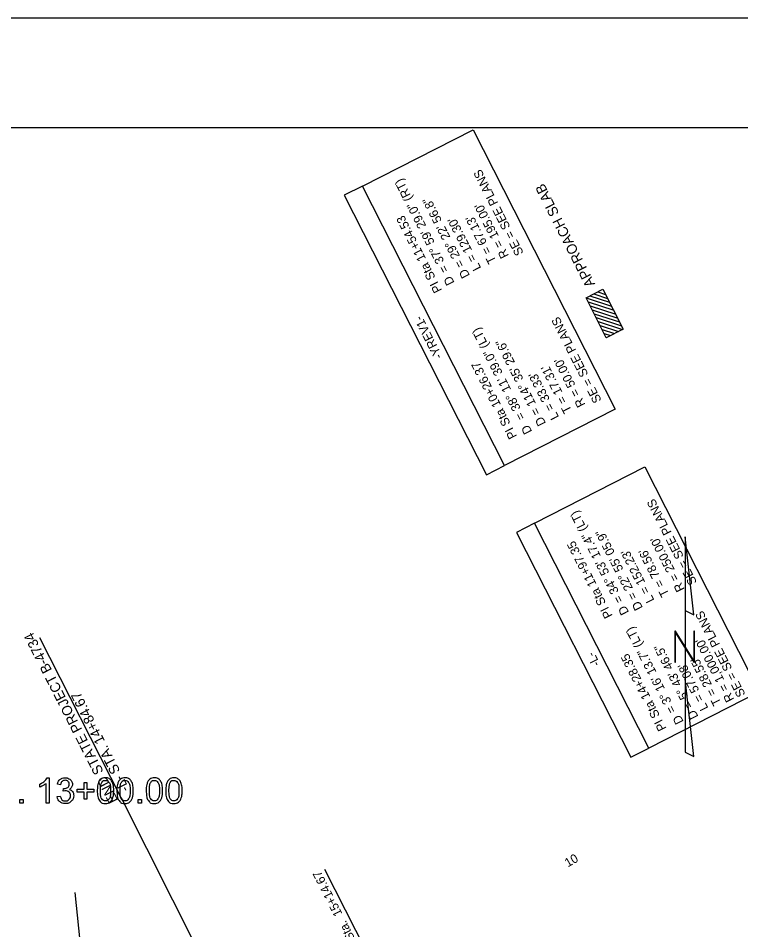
# Model space of a CAD drawing. Extents: x 557583 to 560285, y 513145 to 516544.
# Drawn here: x 559084 to 559658, y 515821 to 516544 of the extents above; entities that cross this region are included whole.
import ezdxf

# ---------------------------------------------------------------- set-up
doc = ezdxf.new("R2010")
doc.units = 0
for name, color, linetype in [('Default', 7, 'Continuous'), ('Exist Environmental Wetland Boundary Cogo Comment', 7, 'Continuous'), ('Exist Environmental Wetland Boundary Cogo Point CELL', 7, 'Continuous'), ('Exist Hydro Jurisdictional Stream or Body of Water NEU Mitigable', 7, 'Continuous'), ('Prop Approach Slab Hatching', 7, 'Continuous'), ('Prop DSN Text', 7, 'Continuous'), ('Scratch_Level_0', 7, 'Continuous'), ('Scratch_Level_3', 7, 'Continuous')]:
    doc.layers.add(name, color=color, linetype=linetype)

# ---------------------------------------------------------------- blocks, each defined once
blk = doc.blocks.new('CTL NORTH ARROW')
at = {"layer": 'Default'}
for points in [[(0.00075, 1.74325), (0.00075, 0.57675), (0.1385, 0.508)], [(-0.16375, -0.247), (-0.15, -0.247), (-0.15, 0.2195), (0.1385, -0.247), (0.152, -0.247), (0.152, 0.2475), (0.1385, 0.2475), (0.1385, -0.21925), (-0.15, 0.2475), (-0.16375, 0.2475)], [(0.00075, -1.6735), (0.1385, -1.74225), (0.00075, -0.5075)]]:
    blk.add_lwpolyline(points, close=True, dxfattribs=at)
blk.add_lwpolyline([(0.00075, 0.57675), (0.00075, -0.5075)], dxfattribs=at)

msp = doc.modelspace()

# ---------------------------------------------------------------- linework, layer by layer
at = {"layer": 'Default'}
msp.add_line((558699.28, 516457.65), (560099.28, 516457.65), dxfattribs=at)
msp.add_lwpolyline([(558489.93, 514310.85), (560284.53, 514310.85), (560284.53, 516544.27), (558489.93, 516544.27)], close=True, dxfattribs=at)
at = {"layer": 'Exist Environmental Wetland Boundary Cogo Point CELL'}
msp.add_line((559365.63, 515793.86), (559327.55, 515868.65), dxfattribs=at)
for points in [[(559470.29, 516189.27), (559357.38, 516411.04), (559445.31, 516455.8), (559558.22, 516234.03)], [(559470.29, 516189.27), (559357.38, 516411.04), (559343.03, 516403.73), (559455.94, 516181.96)], [(559584.89, 515965.02), (559494.02, 516143.5), (559581.65, 516188.12), (559672.52, 516009.64)], [(559584.89, 515965.02), (559494.02, 516143.5), (559479.68, 516136.2), (559570.55, 515957.72)]]:
    msp.add_lwpolyline(points, close=True, dxfattribs=at)
at = {"layer": 'Prop Approach Slab Hatching'}
for p, q in [((559541.16, 516325.53), (559552.11, 516321.96)), ((559544.31, 516327.13), (559550.51, 516325.11)), ((559534.99, 516322.27), (559555.32, 516315.66)), ((559536.6, 516319.12), (559556.92, 516312.51)), ((559538, 516323.92), (559553.72, 516318.81)), ((559538.2, 516315.97), (559558.53, 516309.36)), ((559539.81, 516312.82), (559560.13, 516306.21)), ((559541.41, 516309.67), (559552.29, 516306.13)), ((559542.93, 516306.69), (559563.25, 516300.08)), ((559544.53, 516303.54), (559563.95, 516297.22)), ((559552.21, 516306.3), (559561.65, 516303.23)), ((559546.14, 516300.39), (559560.8, 516295.62)), ((559547.74, 516297.24), (559557.65, 516294.01)), ((559549.34, 516294.09), (559554.5, 516292.41)), ((559550.95, 516290.94), (559551.35, 516290.81))]:
    msp.add_line(p, q, dxfattribs=at)
at = {"layer": 'Prop DSN Text'}
for q in [(559101.33, 516052.47), (559279.8, 515699.18)]:
    msp.add_line((559165.46, 515926.14), q, dxfattribs=at)
msp.add_lwpolyline([(559551.08, 516290.67), (559534.95, 516322.37), (559548.42, 516329.22), (559564.55, 516297.53)], close=True, dxfattribs=at)
at = {"layer": 'Scratch_Level_0'}
for points in [[(559107.15, 515941.44), (559108.73, 515941.44), (559108.73, 515921.36)], [(559101.37, 515934.05), (559101.37, 515936.42)], [(559108.73, 515921.36), (559106.27, 515921.36), (559106.27, 515937.01)], [(559117.74, 515935.81), (559115.28, 515936.26)], [(559136.4, 515924.59), (559136.4, 515930.08), (559130.95, 515930.08), (559130.95, 515932.37), (559136.4, 515932.37), (559136.4, 515937.81), (559138.71, 515937.81), (559138.71, 515932.37), (559144.16, 515932.37), (559144.16, 515930.08), (559138.71, 515930.08), (559138.71, 515924.59), (559136.4, 515924.59)], [(559115.04, 515926.67), (559117.49, 515926.99)], [(559119.88, 515930.84), (559120.15, 515932.99)], [(559085.34, 515921.36), (559085.34, 515924.15), (559088.13, 515924.15), (559088.13, 515921.36), (559085.34, 515921.36)], [(559179.31, 515921.36), (559179.31, 515924.15), (559182.1, 515924.15), (559182.1, 515921.36), (559179.31, 515921.36)]]:
    msp.add_lwpolyline(points, dxfattribs=at)
for points in [[(559101.37, 515936.42), (559103.42, 515937.39), (559104.97, 515938.77), (559106.51, 515940.14), (559107.15, 515941.44)], [(559115.28, 515936.26), (559115.73, 515938.72), (559117.33, 515940.08), (559118.93, 515941.44), (559121.3, 515941.44), (559122.94, 515941.44), (559124.32, 515940.74), (559125.7, 515940.04), (559126.43, 515938.82), (559127.16, 515937.61), (559127.16, 515936.25), (559127.16, 515934.96), (559126.46, 515933.89), (559125.77, 515932.83), (559124.4, 515932.2), (559126.18, 515931.8), (559127.15, 515930.51), (559128.13, 515929.22), (559128.13, 515927.28), (559128.13, 515924.67), (559126.22, 515922.85), (559124.31, 515921.03), (559121.4, 515921.03), (559118.76, 515921.03), (559117.02, 515922.6), (559115.28, 515924.17), (559115.04, 515926.67)], [(559146.87, 515931.23), (559146.87, 515934.77), (559147.6, 515936.94), (559148.33, 515939.1), (559149.77, 515940.27), (559151.2, 515941.44), (559153.39, 515941.44), (559154.99, 515941.44), (559156.21, 515940.79), (559157.43, 515940.14), (559158.22, 515938.92), (559159, 515937.7), (559159.45, 515935.95), (559159.9, 515934.2), (559159.9, 515931.23), (559159.9, 515927.71), (559159.18, 515925.54), (559158.46, 515923.38), (559157.02, 515922.2), (559155.58, 515921.03), (559153.39, 515921.03), (559150.5, 515921.03), (559148.85, 515923.09), (559146.87, 515925.6), (559146.87, 515931.23)], [(559162.4, 515931.23), (559162.4, 515934.77), (559163.13, 515936.94), (559163.86, 515939.1), (559165.3, 515940.27), (559166.74, 515941.44), (559168.92, 515941.44), (559170.53, 515941.44), (559171.74, 515940.79), (559172.96, 515940.14), (559173.75, 515938.92), (559174.54, 515937.7), (559174.99, 515935.95), (559175.44, 515934.2), (559175.44, 515931.23), (559175.44, 515927.71), (559174.71, 515925.54), (559173.99, 515923.38), (559172.55, 515922.2), (559171.11, 515921.03), (559168.92, 515921.03), (559166.03, 515921.03), (559164.38, 515923.09), (559162.4, 515925.6), (559162.4, 515931.23)], [(559185.69, 515931.23), (559185.69, 515934.77), (559186.42, 515936.94), (559187.15, 515939.1), (559188.59, 515940.27), (559190.03, 515941.44), (559192.21, 515941.44), (559193.82, 515941.44), (559195.04, 515940.79), (559196.25, 515940.14), (559197.04, 515938.92), (559197.83, 515937.7), (559198.28, 515935.95), (559198.73, 515934.2), (559198.73, 515931.23), (559198.73, 515927.71), (559198.01, 515925.54), (559197.28, 515923.38), (559195.84, 515922.2), (559194.41, 515921.03), (559192.21, 515921.03), (559189.32, 515921.03), (559187.67, 515923.09), (559185.69, 515925.6), (559185.69, 515931.23)], [(559201.23, 515931.23), (559201.23, 515934.77), (559201.96, 515936.94), (559202.69, 515939.1), (559204.13, 515940.27), (559205.56, 515941.44), (559207.75, 515941.44), (559209.35, 515941.44), (559210.57, 515940.79), (559211.79, 515940.14), (559212.58, 515938.92), (559213.36, 515937.7), (559213.81, 515935.95), (559214.26, 515934.2), (559214.26, 515931.23), (559214.26, 515927.71), (559213.54, 515925.54), (559212.82, 515923.38), (559211.38, 515922.2), (559209.94, 515921.03), (559207.75, 515921.03), (559204.85, 515921.03), (559203.21, 515923.09), (559201.23, 515925.6), (559201.23, 515931.23)], [(559106.27, 515937.01), (559105.39, 515936.16), (559103.95, 515935.32), (559102.51, 515934.47), (559101.37, 515934.05)], [(559120.15, 515932.99), (559120.4, 515932.97), (559120.55, 515932.97), (559122.12, 515932.97), (559123.37, 515933.78), (559124.63, 515934.6), (559124.63, 515936.31), (559124.63, 515937.66), (559123.71, 515938.54), (559122.8, 515939.43), (559121.35, 515939.43), (559119.92, 515939.43), (559118.97, 515938.52), (559118.01, 515937.62), (559117.74, 515935.81)], [(559149.4, 515931.23), (559149.4, 515926.29), (559150.55, 515924.67), (559151.7, 515923.04), (559153.39, 515923.04), (559155.07, 515923.04), (559156.22, 515924.67), (559157.37, 515926.31), (559157.37, 515931.23), (559157.37, 515936.16), (559156.22, 515937.79), (559155.08, 515939.41), (559153.36, 515939.41), (559151.67, 515939.41), (559150.66, 515937.98), (559149.4, 515936.15), (559149.4, 515931.23)], [(559164.93, 515931.23), (559164.93, 515926.29), (559166.08, 515924.67), (559167.23, 515923.04), (559168.92, 515923.04), (559170.61, 515923.04), (559171.76, 515924.67), (559172.91, 515926.31), (559172.91, 515931.23), (559172.91, 515936.16), (559171.76, 515937.79), (559170.61, 515939.41), (559168.89, 515939.41), (559167.2, 515939.41), (559166.19, 515937.98), (559164.93, 515936.15), (559164.93, 515931.23)], [(559188.23, 515931.23), (559188.23, 515926.29), (559189.37, 515924.67), (559190.52, 515923.04), (559192.21, 515923.04), (559193.9, 515923.04), (559195.05, 515924.67), (559196.2, 515926.31), (559196.2, 515931.23), (559196.2, 515936.16), (559195.05, 515937.79), (559193.9, 515939.41), (559192.18, 515939.41), (559190.5, 515939.41), (559189.49, 515937.98), (559188.23, 515936.15), (559188.23, 515931.23)], [(559203.76, 515931.23), (559203.76, 515926.29), (559204.91, 515924.67), (559206.06, 515923.04), (559207.75, 515923.04), (559209.43, 515923.04), (559210.58, 515924.67), (559211.73, 515926.31), (559211.73, 515931.23), (559211.73, 515936.16), (559210.58, 515937.79), (559209.44, 515939.41), (559207.72, 515939.41), (559206.03, 515939.41), (559205.02, 515937.98), (559203.76, 515936.15), (559203.76, 515931.23)], [(559117.49, 515926.99), (559117.92, 515924.9), (559118.93, 515923.98), (559119.94, 515923.05), (559121.41, 515923.05), (559123.15, 515923.05), (559124.34, 515924.26), (559125.53, 515925.46), (559125.53, 515927.23), (559125.53, 515928.92), (559124.42, 515930.02), (559123.32, 515931.12), (559121.61, 515931.12), (559120.92, 515931.12), (559119.88, 515930.84)]]:
    msp.add_open_spline(points, degree=3, dxfattribs=at)
at = {"layer": 'Scratch_Level_3'}
msp.add_line((559129.15, 515850.4), (559148.98, 515654.78), dxfattribs=at)

# ---------------------------------------------------------------- block references
at = {"layer": 'Default', "xscale": 50, "yscale": 50}
msp.add_blockref('CTL NORTH ARROW', (559613.56, 516045.44), dxfattribs=at)

# ---------------------------------------------------------------- texts
at = {"layer": 'Exist Environmental Wetland Boundary Cogo Comment'}
msp.add_text('10', height=7, rotation=30.25241, dxfattribs=at).set_placement((559520.53, 515870.27))
at = {"layer": 'Exist Environmental Wetland Boundary Cogo Point CELL'}
msp.add_text('POT Sta.  15+14.67', height=7, rotation=116.98193, dxfattribs=at).set_placement((559361.52, 515794.55))
at = {"layer": 'Exist Hydro Jurisdictional Stream or Body of Water NEU Mitigable'}
for s, p in [('SE = SEE PLANS', (559485.59, 516357.96)), ('= 37%%d 59\' 29.0" (RT)', (559426.22, 516344.25)), ('D = 29%%d 22\' 56.8"', (559442.94, 516340.05)), ("R = 195.00'", (559473.85, 516355.78)), ('PI Sta 11+54.53', (559420.82, 516328.36)), ("L = 129.30'", (559451.89, 516345.93)), ("T = 67.13'", (559463.97, 516351.52)), ('D', (559430.72, 516334.4)), ('-YREV1-', (559421.18, 516275.92)), ('SE = SEE PLANS', (559547.5, 516240.98)), ('= 38%%d 11\' 39.0" (LT)', (559486.95, 516227.43)), ('D = 114%%d 35\' 29.6"', (559503.33, 516222.79)), ('PI Sta 10+26.37', (559480.36, 516212.46)), ("T = 17.31'", (559523.86, 516232.83)), ("R = 50.00'", (559534.69, 516237.62)), ("L = 33.33'", (559513.68, 516227.64)), ('D', (559492.35, 516216.26)), ('SE = SEE PLANS', (559623.27, 516096.53)), ('= 34%%d 53\' 17.4" (LT)', (559564.91, 516082.1)), ('D = 22%%d 55\' 05.9"', (559580.3, 516076.4)), ('PI Sta 11+97.35', (559556.26, 516070.06)), ("R = 250.00'", (559613.47, 516091.11)), ("L = 152.23'", (559589.43, 516082.35)), ("T = 78.56'", (559601.24, 516087.17)), ('D', (559569.3, 516072.76)), ('SE = SEE PLANS', (559661.75, 516007.63)), ('= 3%%d 16\' 13.7" (LT)', (559606.68, 515994.64)), ("R = 1,000.00'", (559652.81, 516003.64)), ('D = 5%%d 43\' 46.5"', (559624.35, 515989.98)), ('-L-', (559546.35, 516031.79)), ('PI Sta 14+28.35', (559598.99, 515980.64)), ("T = 28.55'", (559642.57, 516000.84)), ("L = 57.08'", (559632.26, 515996.75)), ('D', (559612.64, 515986.02))]:
    msp.add_text(s, height=7, rotation=116.98193, dxfattribs=at).set_placement(p)
at = {"layer": 'Prop DSN Text'}
for s, p in [('APPROACH SLAB', (559542.39, 516333.29)), ('END STATE PROJECT B-4734', (559163.67, 515923.56)), ('-L- STA. 14+84.67', (559172.57, 515932.47))]:
    msp.add_text(s, height=8, rotation=116.98193, dxfattribs=at).set_placement(p)

doc.saveas('drawing.dxf')
